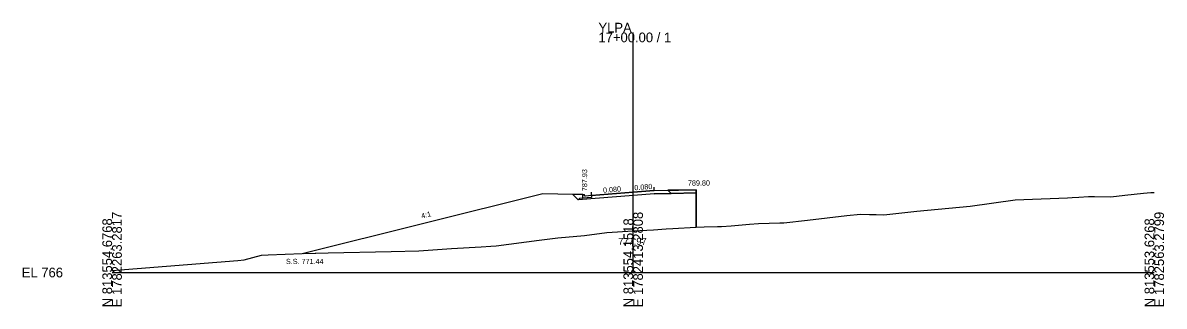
# Model space of a CAD drawing. Extents: x -76 to 1303, y -10 to 9544.
# Drawn here: x -25.7 to 302.8, y 6990.3 to 7071.9 of the extents above; entities that cross this region are included whole.
import ezdxf

# ---------------------------------------------------------------- set-up
doc = ezdxf.new("R2010")
doc.units = 0
for name, color, linetype in [('Exist Cross Section Cell', 7, 'Continuous'), ('Exist XS Center Line Elevation Label', 7, 'Continuous'), ('Exist XS Ground Line', 7, 'Continuous'), ('Prop XS Ditch Standard Text', 7, 'Continuous'), ('Prop XS Dump Level', 7, 'Continuous'), ('Prop XS Earthwork Shape', 7, 'Continuous'), ('Prop XS EOT Tick Mark', 7, 'Continuous'), ('Prop XS Finish Grade', 7, 'Continuous'), ('Prop XS Finish Grade CurbGutter', 7, 'Continuous'), ('Prop XS Finish Grade Earthwork', 7, 'Continuous'), ('Prop XS Finish Grade Paved Shoulder', 7, 'Continuous'), ('Prop XS Finish Grade Pavement', 7, 'Continuous'), ('Prop XS Hydro Elevations', 7, 'Continuous'), ('Prop XS Pvmt Edge Slope', 7, 'Continuous'), ('Prop XS SE Text', 7, 'Continuous'), ('Prop XS Side Slope Text', 7, 'Continuous'), ('Prop XS SS Elevation Text', 7, 'Continuous'), ('Prop XS Subgrade CurbGutter', 7, 'Continuous'), ('Prop XS Subgrade Earthwork', 7, 'Continuous'), ('Scratch_Level_3', 7, 'Continuous')]:
    doc.layers.add(name, color=color, linetype=linetype)

msp = doc.modelspace()

# ---------------------------------------------------------------- linework, layer by layer
at = {"layer": 'Exist Cross Section Cell'}
for p, q in [((150, 7000), (150, 7069.1)), ((0, 7000), (150, 7000)), ((150, 7000), (300, 7000))]:
    msp.add_line(p, q, dxfattribs=at)
at = {"layer": 'Exist XS Ground Line'}
for p, q in [((246.96, 7019.08), (259.93, 7020.92)), ((259.93, 7020.92), (262.45, 7021.02)), ((262.45, 7021.02), (274.99, 7021.51)), ((274.99, 7021.51), (276.31, 7021.58)), ((276.31, 7021.58), (278.23, 7021.73)), ((278.23, 7021.73), (281.06, 7021.9)), ((281.06, 7021.9), (282.78, 7021.87)), ((282.78, 7021.87), (287.47, 7021.81)), ((287.47, 7021.81), (291.55, 7022.27)), ((291.55, 7022.27), (296.92, 7022.82)), ((296.92, 7022.82), (297.91, 7022.93)), ((297.91, 7022.93), (299.02, 7023.01)), ((299.02, 7023.01), (300, 7023.03)), ((222.19, 7016.62), (231.63, 7017.63)), ((231.63, 7017.63), (246.96, 7019.08)), ((186.07, 7014.11), (192.17, 7014.32)), ((192.17, 7014.32), (193.32, 7014.34)), ((193.32, 7014.34), (200.13, 7015.08)), ((200.13, 7015.08), (211.49, 7016.46)), ((211.49, 7016.46), (215.44, 7016.78)), ((215.44, 7016.78), (218.02, 7016.66)), ((218.02, 7016.66), (219.9, 7016.71)), ((219.9, 7016.71), (222.19, 7016.62)), ((135.99, 7010.7), (142.38, 7011.53)), ((142.38, 7011.53), (143.94, 7011.64)), ((143.94, 7011.64), (148.46, 7011.88)), ((148.46, 7011.88), (150, 7011.97)), ((150, 7011.97), (155.8, 7012.3)), ((155.8, 7012.3), (159.49, 7012.55)), ((159.49, 7012.55), (161.4, 7012.66)), ((161.4, 7012.66), (168.02, 7013.1)), ((168.02, 7013.1), (170.47, 7013.17)), ((170.47, 7013.17), (174.24, 7013.26)), ((174.24, 7013.26), (175.44, 7013.27)), ((175.44, 7013.27), (178.16, 7013.44)), ((178.16, 7013.44), (183.46, 7013.9)), ((183.46, 7013.9), (186.07, 7014.11)), ((109.04, 7007.56), (110.51, 7007.72)), ((110.51, 7007.72), (122.95, 7009.29)), ((122.95, 7009.29), (128.27, 7009.95)), ((128.27, 7009.95), (135.99, 7010.7)), ((37.99, 7003.63), (42.99, 7004.98)), ((42.99, 7004.98), (44.89, 7005.07)), ((44.89, 7005.07), (54.67, 7005.43)), ((54.67, 7005.43), (62.19, 7005.64)), ((62.19, 7005.64), (80.37, 7006.06)), ((80.37, 7006.06), (88.27, 7006.28)), ((88.27, 7006.28), (97.73, 7006.91)), ((97.73, 7006.91), (106.25, 7007.38)), ((106.25, 7007.38), (109.04, 7007.56)), ((1.17, 7000.65), (36.24, 7003.42)), ((36.24, 7003.42), (37.99, 7003.63)), ((0, 7000.62), (1.17, 7000.65))]:
    msp.add_line(p, q, dxfattribs=at)
at = {"layer": 'Prop XS Dump Level'}
for p, q in [((150, 7023.13), (138, 7022.17)), ((156, 7023.61), (150, 7023.13))]:
    msp.add_line(p, q, dxfattribs=at)
at = {"layer": 'Prop XS Earthwork Shape'}
msp.add_lwpolyline([(97.73, 7006.91), (106.25, 7007.38), (109.04, 7007.56), (110.51, 7007.72), (122.95, 7009.29), (128.27, 7009.95), (135.99, 7010.7), (142.38, 7011.53), (143.94, 7011.64), (148.46, 7011.88), (150, 7011.97), (155.8, 7012.3), (159.49, 7012.55), (161.4, 7012.66), (168.02, 7013.1), (168.13, 7013.1), (168.13, 7022.94), (160.9, 7022.79), (156.05, 7022.7), (150.07, 7022.22), (134.16, 7020.94), (132.61, 7022.49), (124, 7022.67), (55.06, 7005.44), (62.19, 7005.64), (80.37, 7006.06), (88.27, 7006.28)], close=True, dxfattribs=at)
at = {"layer": 'Prop XS EOT Tick Mark'}
for p, q in [((156, 7023.61), (156, 7024.61)), ((138, 7022.17), (138, 7023.17))]:
    msp.add_line(p, q, dxfattribs=at)
at = {"layer": 'Prop XS Finish Grade'}
for p, q in [((135.5, 7022.43), (132.61, 7022.49)), ((160, 7023.69), (163, 7023.75)), ((163, 7023.75), (168.13, 7023.8)), ((168.13, 7023.8), (168.13, 7022.94))]:
    msp.add_line(p, q, dxfattribs=at)
at = {"layer": 'Prop XS Finish Grade CurbGutter'}
for p, q in [((135.5, 7022.43), (135.75, 7022.43)), ((135.75, 7022.43), (135.88, 7022.42)), ((135.97, 7022.33), (135.88, 7022.42)), ((136.03, 7022.08), (135.97, 7022.33)), ((136.13, 7021.98), (136.03, 7022.08)), ((136.25, 7021.96), (136.13, 7021.98)), ((138, 7022.17), (136.25, 7021.96))]:
    msp.add_line(p, q, dxfattribs=at)
at = {"layer": 'Prop XS Finish Grade Earthwork'}
for p, q in [((124, 7022.67), (55.06, 7005.44)), ((132.61, 7022.49), (124, 7022.67)), ((168.13, 7022.94), (168.13, 7013.1))]:
    msp.add_line(p, q, dxfattribs=at)
at = {"layer": 'Prop XS Finish Grade Paved Shoulder'}
msp.add_line((156, 7023.61), (160, 7023.69), dxfattribs=at)
at = {"layer": 'Prop XS Finish Grade Pavement'}
for p, q in [((138, 7022.17), (150, 7023.13)), ((150, 7023.13), (156, 7023.61))]:
    msp.add_line(p, q, dxfattribs=at)
at = {"layer": 'Prop XS Pvmt Edge Slope'}
for p, q in [((134.5, 7021.31), (134.16, 7020.94)), ((135.5, 7021.39), (134.5, 7021.31)), ((160, 7023.69), (160.9, 7022.79))]:
    msp.add_line(p, q, dxfattribs=at)
at = {"layer": 'Prop XS Subgrade CurbGutter'}
for p, q in [((135.5, 7021.39), (135.5, 7022.43)), ((138, 7021.59), (135.5, 7021.39)), ((138, 7022.17), (138, 7021.59))]:
    msp.add_line(p, q, dxfattribs=at)
at = {"layer": 'Prop XS Subgrade Earthwork'}
for p, q in [((134.16, 7020.94), (132.61, 7022.49)), ((150.07, 7022.22), (134.16, 7020.94)), ((156.05, 7022.7), (150.07, 7022.22)), ((156.05, 7022.7), (160.9, 7022.79)), ((160.9, 7022.79), (168.13, 7022.94))]:
    msp.add_line(p, q, dxfattribs=at)
at = {"layer": 'Scratch_Level_3'}
for p, q in [((163, 7023.75), (160, 7023.69)), ((160, 7023.69), (160.9, 7022.79)), ((160.9, 7022.79), (168.13, 7022.94)), ((168.13, 7023.8), (163, 7023.75)), ((168.13, 7022.94), (168.13, 7023.8))]:
    msp.add_line(p, q, dxfattribs=at)

# ---------------------------------------------------------------- texts
at = {"layer": 'Exist Cross Section Cell'}
for s, p in [('YLPA', (140, 7069.1)), ('17+00.00 / 1', (140, 7066.3)), ('EL 766', (-26, 6998.6))]:
    msp.add_text(s, height=2.8, dxfattribs=at).set_placement(p)
for s, p in [('N 813554.6768', (0, 6990)), ('E 1782263.2817', (2.8, 6990)), ('N 813554.1518', (150, 6990)), ('E 1782413.2808', (152.8, 6990)), ('N 813553.6268', (300, 6990)), ('E 1782563.2799', (302.8, 6990))]:
    msp.add_text(s, height=2.8, rotation=90, dxfattribs=at).set_placement(p)
at = {"layer": 'Exist XS Center Line Elevation Label'}
msp.add_text('777.97', height=2, dxfattribs=at).set_placement((145.7, 7007.97))
at = {"layer": 'Prop XS Ditch Standard Text'}
msp.add_text('789.80', height=1.5, dxfattribs=at).set_placement((165.76, 7025.03))
at = {"layer": 'Prop XS Dump Level'}
msp.add_text('Case4', height=0.04, dxfattribs=at).set_placement((168, 7023.41))
at = {"layer": 'Prop XS Hydro Elevations'}
msp.add_text('787.93', height=1.5, rotation=90, dxfattribs=at).set_placement((136.75, 7023.43))
at = {"layer": 'Prop XS SE Text'}
for p in [(141.38, 7022.94), (150.38, 7023.66)]:
    msp.add_text('0.080', height=1.5, rotation=4.5739, dxfattribs=at).set_placement(p)
at = {"layer": 'Prop XS Side Slope Text'}
msp.add_text('4:1', height=1.5, rotation=14.0362, dxfattribs=at).set_placement((89.17, 7015.51))
at = {"layer": 'Prop XS SS Elevation Text'}
msp.add_text('S.S. 771.44', height=1.5, dxfattribs=at).set_placement((50.05, 7002.44))

doc.saveas('drawing.dxf')
